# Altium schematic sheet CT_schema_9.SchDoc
size 274 x 160 mm
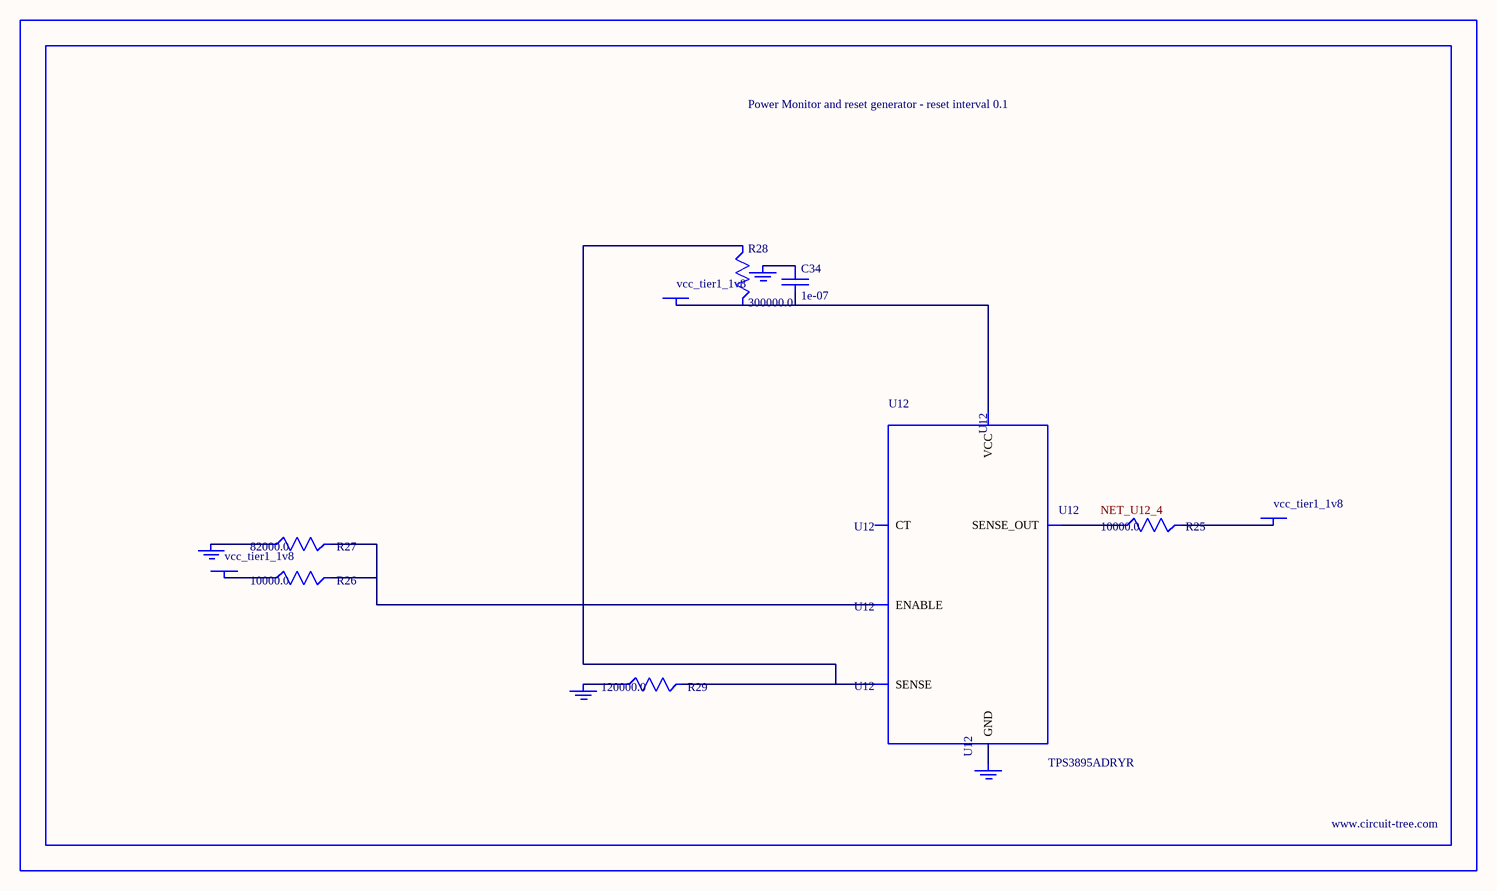
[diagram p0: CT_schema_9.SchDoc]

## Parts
BORDER8  (no value)
C34  1e-07  [C0402]
GND_INSTANCE_8_0  (no value)
GND_INSTANCE_8_1  (no value)
GND_INSTANCE_8_2  (no value)
GND_INSTANCE_8_3  (no value)
POWER_INSTANCE_8_0  vcc_tier1_1v8
POWER_INSTANCE_8_1  vcc_tier1_1v8
POWER_INSTANCE_8_2  vcc_tier1_1v8
R25  10000.0  [R0603]
R26  10000.0  [R0603]
R27  82000.0  [R0603]
R28  300000.0  [R0603]
R29  120000.0  [R0603]
U12  TPS3895ADRYR  [SON-6]

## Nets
NetC34_1: C34.1 GND_INSTANCE_8_2.0(GND)
NetC34_2: C34.2 POWER_INSTANCE_8_2.0(PWR) R28.2 U12.6(VCC)
NetGND_INSTANCE_8_0_0: GND_INSTANCE_8_0.0(GND) R27.1
NetGND_INSTANCE_8_1_0: GND_INSTANCE_8_1.0(GND) R29.1
NetGND_INSTANCE_8_3_0: GND_INSTANCE_8_3.0(GND) U12.2(GND)
NetPOWER_INSTANCE_8_0_0: POWER_INSTANCE_8_0.0(PWR) R26.1
NetPOWER_INSTANCE_8_1_0: POWER_INSTANCE_8_1.0(PWR) R25.2
NetR25_1: R25.1 U12.4(SENSE_OUT)
NetR26_2: R26.2 R27.2 U12.1(ENABLE)
NetR28_1: R28.1 R29.2 U12.3(SENSE)

Not connected (* = marked no-connect by the designer): U12 5(CT)

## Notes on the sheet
- Labels drawn without touching a wire or pin: NET_U12_4

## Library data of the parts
BORDER8 = BORDER_PAGE8
C34 = C0402C104K3RACTU
GND_INSTANCE_8_0-GND_INSTANCE_8_3 = GND
POWER_INSTANCE_8_0-POWER_INSTANCE_8_2 = PWR
R25 R26 = RC0603JR-0710KL
R27 = RC0603JR-0782KL
R28 = RC0603JR-07300KL
R29 = RC0603JR-07120KL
